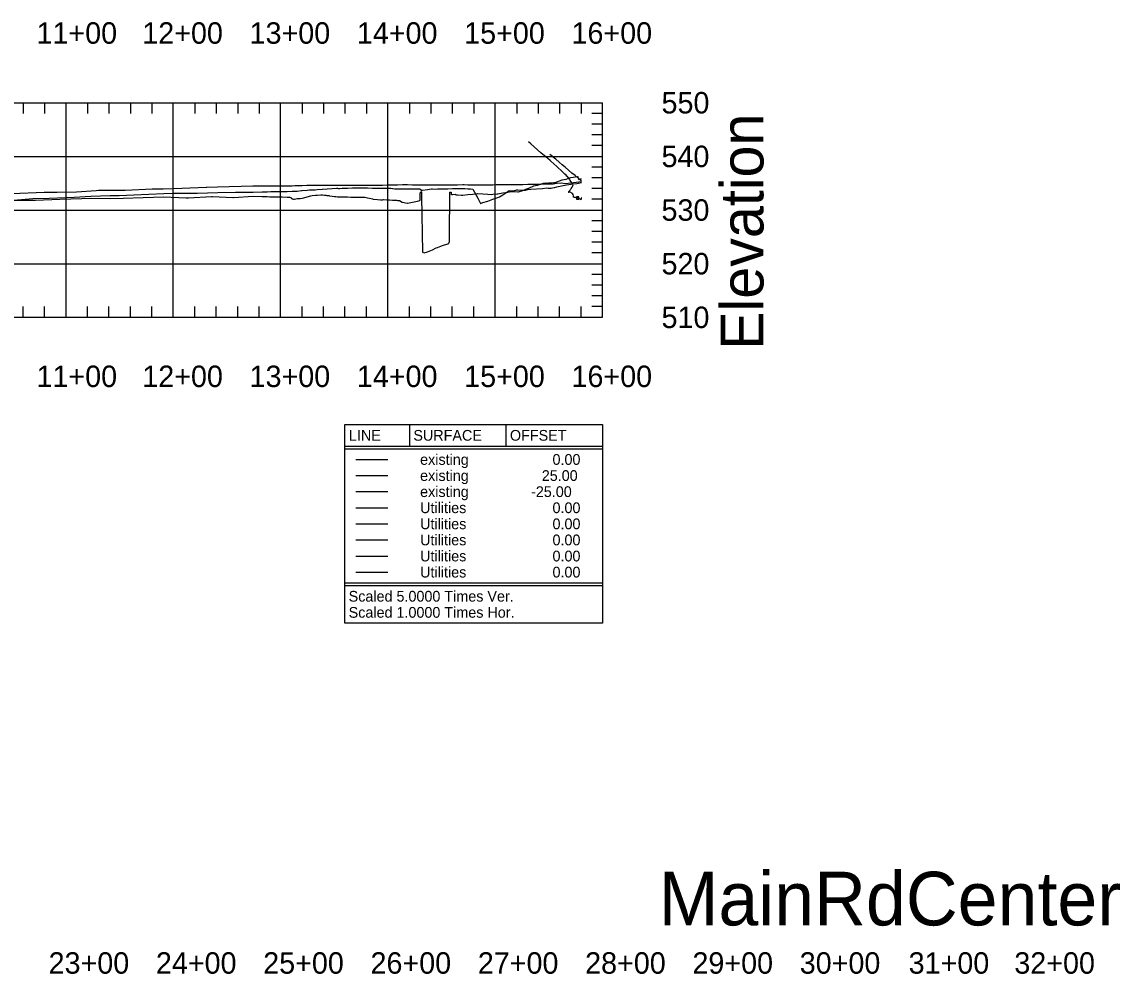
# Model space of a CAD drawing. Extents: x 704797 to 712284, y 374940 to 376945.
# Drawn here: x 709378 to 710402, y 375980 to 376868 of the extents above; entities that cross this region are included whole.
import ezdxf

# ---------------------------------------------------------------- set-up
doc = ezdxf.new("R2010")
doc.units = 0
for name, color, linetype in [('1', 7, 'Continuous'), ('10', 7, 'Continuous'), ('13', 7, 'Continuous'), ('61', 7, 'Continuous'), ('63', 7, 'Continuous'), ('Default_Profile', 7, 'Continuous'), ('Existing', 7, 'Continuous')]:
    doc.layers.add(name, color=color, linetype=linetype)

msp = doc.modelspace()

# ---------------------------------------------------------------- linework, layer by layer
at = {"layer": '10'}
msp.add_lwpolyline([(709899.8, 376703.6), (709899.5, 376703.8), (709899.5, 376702.5), (709899.4, 376701.7), (709897.5, 376703), (709896.9, 376703.5), (709895.6, 376703.6), (709895.5, 376703.6), (709895.3, 376703.6), (709895.1, 376703.6), (709894.8, 376703.7), (709894.2, 376703.9), (709893.3, 376704.1), (709892.5, 376704.3), (709892.5, 376705), (709892.4, 376705.6), (709892.3, 376706.9), (709891.6, 376707.7), (709889.5, 376708.8), (709888.8, 376709), (709888.5, 376709), (709888.3, 376709), (709887.4, 376708.8), (709887.5, 376708.9), (709887.7, 376709.1), (709888.3, 376709.6), (709888.4, 376709.8), (709889, 376710.4), (709889.2, 376710.7), (709889.7, 376711.3), (709889.9, 376711.6), (709890.4, 376712.5), (709891.1, 376713.6), (709891.8, 376715), (709892.3, 376715.8), (709891.9, 376716.4), (709889.3, 376719.7), (709889.2, 376720), (709889, 376720.3), (709888.6, 376721.1), (709886.9, 376723.6), (709886.4, 376724), (709885.6, 376724.7), (709884.5, 376725.7), (709882.2, 376727.8), (709876.9, 376733), (709871.3, 376737.9), (709870.6, 376738.5), (709868.4, 376740.3), (709862.1, 376745.5), (709858.9, 376748.5), (709852.7, 376753.9), (709850.4, 376755.8)], dxfattribs=at)
msp.add_lwpolyline([(709895.3, 376702.5), (709897.3, 376702.5), (709897.3, 376704.5), (709895.3, 376704.5)], close=True, dxfattribs=at)
at = {"layer": '13'}
msp.add_lwpolyline([(709899.8, 376719.3), (709898.6, 376720.4), (709897.2, 376721.6), (709893.9, 376724.4), (709891, 376726.7), (709887.7, 376729.5), (709884.7, 376732.1), (709881.9, 376734.4), (709879, 376736.9), (709875.9, 376739.6), (709873.8, 376741.4), (709872.9, 376742.1), (709870.3, 376744.1)], dxfattribs=at)
at = {"layer": '61'}
for p, q in [((708419.5, 376792.3), (709919.5, 376792.3)), ((709379.5, 376792.3), (709379.5, 376782.3)), ((709399.5, 376792.3), (709399.5, 376782.3)), ((709419.5, 376592.3), (709419.5, 376792.3)), ((709439.5, 376792.3), (709439.5, 376782.3)), ((709459.5, 376792.3), (709459.5, 376782.3)), ((709479.5, 376792.3), (709479.5, 376782.3)), ((709499.5, 376792.3), (709499.5, 376782.3)), ((709519.5, 376592.3), (709519.5, 376792.3)), ((709539.5, 376792.3), (709539.5, 376782.3)), ((709559.5, 376792.3), (709559.5, 376782.3)), ((709579.5, 376792.3), (709579.5, 376782.3)), ((709599.5, 376792.3), (709599.5, 376782.3)), ((709619.5, 376592.3), (709619.5, 376792.3)), ((709639.5, 376792.3), (709639.5, 376782.3)), ((709659.5, 376792.3), (709659.5, 376782.3)), ((709679.5, 376792.3), (709679.5, 376782.3)), ((709699.5, 376792.3), (709699.5, 376782.3)), ((709719.5, 376592.3), (709719.5, 376792.3)), ((709739.5, 376792.3), (709739.5, 376782.3)), ((709759.5, 376792.3), (709759.5, 376782.3)), ((709779.5, 376792.3), (709779.5, 376782.3)), ((709799.5, 376792.3), (709799.5, 376782.3)), ((709819.5, 376592.3), (709819.5, 376792.3)), ((709839.5, 376792.3), (709839.5, 376782.3)), ((709859.5, 376792.3), (709859.5, 376782.3)), ((709879.5, 376792.3), (709879.5, 376782.3)), ((709899.5, 376792.3), (709899.5, 376782.3)), ((709919.5, 376592.3), (709919.5, 376792.3)), ((709919.5, 376782.3), (709909.5, 376782.3)), ((709919.5, 376772.3), (709909.5, 376772.3)), ((709919.5, 376762.3), (709909.5, 376762.3)), ((709919.5, 376752.3), (709909.5, 376752.3)), ((708419.5, 376742.3), (709919.5, 376742.3)), ((709919.5, 376732.3), (709909.5, 376732.3)), ((709919.5, 376722.3), (709909.5, 376722.3)), ((709919.5, 376712.3), (709909.5, 376712.3)), ((709919.5, 376702.3), (709909.5, 376702.3)), ((708419.5, 376692.3), (709919.5, 376692.3)), ((709919.5, 376682.3), (709909.5, 376682.3)), ((709919.5, 376672.3), (709909.5, 376672.3)), ((709919.5, 376662.3), (709909.5, 376662.3)), ((709919.5, 376652.3), (709909.5, 376652.3)), ((708419.5, 376642.3), (709919.5, 376642.3)), ((709919.5, 376632.3), (709909.5, 376632.3)), ((709919.5, 376622.3), (709909.5, 376622.3)), ((709919.5, 376612.3), (709909.5, 376612.3)), ((709379.5, 376592.3), (709379.5, 376602.3)), ((709399.5, 376592.3), (709399.5, 376602.3)), ((709439.5, 376592.3), (709439.5, 376602.3)), ((709459.5, 376592.3), (709459.5, 376602.3)), ((709479.5, 376592.3), (709479.5, 376602.3)), ((709499.5, 376592.3), (709499.5, 376602.3)), ((709539.5, 376592.3), (709539.5, 376602.3)), ((709559.5, 376592.3), (709559.5, 376602.3)), ((709579.5, 376592.3), (709579.5, 376602.3)), ((709599.5, 376592.3), (709599.5, 376602.3)), ((709639.5, 376592.3), (709639.5, 376602.3)), ((709659.5, 376592.3), (709659.5, 376602.3)), ((709679.5, 376592.3), (709679.5, 376602.3)), ((709699.5, 376592.3), (709699.5, 376602.3)), ((709739.5, 376592.3), (709739.5, 376602.3)), ((709759.5, 376592.3), (709759.5, 376602.3)), ((709779.5, 376592.3), (709779.5, 376602.3)), ((709799.5, 376592.3), (709799.5, 376602.3)), ((709839.5, 376592.3), (709839.5, 376602.3)), ((709859.5, 376592.3), (709859.5, 376602.3)), ((709879.5, 376592.3), (709879.5, 376602.3)), ((709899.5, 376592.3), (709899.5, 376602.3)), ((709919.5, 376602.3), (709909.5, 376602.3)), ((708419.5, 376592.3), (709919.5, 376592.3)), ((709739.5, 376492.3), (709739.5, 376472.3)), ((709829.5, 376492.3), (709829.5, 376472.3)), ((709679.5, 376472.3), (709919.5, 376472.3)), ((709679.5, 376469.8), (709919.5, 376469.8)), ((709679.5, 376344.8), (709919.5, 376344.8)), ((709679.5, 376342.3), (709919.5, 376342.3))]:
    msp.add_line(p, q, dxfattribs=at)
msp.add_lwpolyline([(709679.5, 376492.3), (709919.5, 376492.3), (709919.5, 376307.3), (709679.5, 376307.3)], close=True, dxfattribs=at)
at = {"layer": '63'}
for p, q in [((709689.5, 376444.8), (709719.5, 376444.8)), ((709689.5, 376429.8), (709719.5, 376429.8))]:
    msp.add_line(p, q, dxfattribs=at)
for points in [[(709353, 376701.4), (709383.9, 376701.4), (709391, 376701.6), (709413.7, 376702.4), (709434.3, 376702.9), (709443, 376703.3), (709461.3, 376703.1), (709473.1, 376703.3), (709491.5, 376704), (709510.6, 376704.5), (709531.6, 376703.6), (709533, 376703.7), (709533, 376703.7), (709533.1, 376703.7), (709533.1, 376703.7), (709533.2, 376703.7), (709533.2, 376703.7), (709533.6, 376703.7), (709533.8, 376703.6), (709555, 376704.9), (709556, 376705), (709575, 376704), (709575.6, 376704), (709593.8, 376705.3), (709602.3, 376705), (709606.9, 376704.8), (709609.4, 376704.7), (709611.6, 376704.7), (709616.3, 376704.6), (709621, 376704.5), (709625.6, 376704.4), (709628.1, 376704.3), (709629.4, 376703.6), (709629.6, 376703.2), (709630, 376702.9), (709630.3, 376702.8), (709630.6, 376702.7), (709631.4, 376702.5), (709632.4, 376702.5), (709633.6, 376702.6), (709635, 376702.9), (709636.1, 376703.1), (709637.7, 376703), (709639.7, 376703.5), (709641, 376703.8), (709644.3, 376704.7), (709644.3, 376704.7), (709647.8, 376705.5), (709649, 376705.7), (709652.1, 376706.1), (709653.7, 376706.2), (709656.9, 376706.4), (709657.8, 376706.4), (709658.3, 376706.4), (709658.6, 376706.4), (709660.5, 376706.3), (709660.9, 376706.1), (709661.8, 376706), (709662.7, 376705.9), (709663, 376705.9), (709664.4, 376705.7), (709665, 376705.5), (709667.7, 376705.2), (709669.7, 376704.8), (709669.9, 376704.9), (709670.9, 376704.8), (709672.4, 376704.7), (709677, 376704.6), (709677.3, 376704.6), (709681.7, 376704.5), (709685, 376704.4), (709686.4, 376704.4), (709691.1, 376704.4), (709691.9, 376704.3), (709695.7, 376704.3), (709698, 376704.2), (709700.4, 376703.8), (709702.3, 376703.5), (709705.1, 376702.6), (709705.9, 376702.3), (709709.8, 376702), (709712.5, 376701.8), (709714.4, 376701.9), (709715.5, 376702), (709718.5, 376701.8), (709719.1, 376701.7), (709719.8, 376701.7), (709721, 376701.7), (709723.8, 376701.6), (709727.4, 376701.4), (709728.4, 376701.3), (709730.4, 376701.1), (709732.8, 376699.7), (709733.1, 376699.6), (709737.3, 376698.6), (709737.4, 376698.6), (709737.8, 376698.7), (709742.5, 376699.7), (709747.1, 376700.7), (709749.3, 376701.1), (709749.3, 376701.1), (709749.5, 376702.1), (709749.7, 376708.1), (709749.7, 376708.1), (709750.6, 376709.3), (709750.7, 376709.4), (709750.8, 376706.8), (709750.9, 376704.9), (709751.7, 376653.2), (709751.8, 376653.1), (709753.4, 376652.3), (709756.5, 376653.4), (709761, 376655.1), (709761.2, 376655.2), (709764.5, 376657.1), (709765.8, 376657.5), (709770.5, 376659.1), (709775.2, 376660.7), (709776.2, 376661), (709776.7, 376662.3), (709777, 376662.3), (709777, 376667.7), (709777.3, 376708.9), (709777.4, 376708.9), (709777.5, 376708.9), (709778.3, 376709.1), (709778.5, 376707), (709778.6, 376706.5), (709778.7, 376706.7), (709779.8, 376706.9), (709782.1, 376707.2), (709782.8, 376706.5), (709783.7, 376706.6), (709784.5, 376706.6), (709788.2, 376706.2), (709789.2, 376706.3), (709793.9, 376706.8), (709798.5, 376707.2), (709803.1, 376707.6), (709803.2, 376707.6), (709807.9, 376707.4), (709812.6, 376707.1), (709816, 376706.9), (709817.2, 376707), (709821.3, 376707.3), (709821.9, 376707.4), (709826.6, 376708.2), (709831.2, 376709), (709834.6, 376709.5), (709835.9, 376709.5), (709840.6, 376709.4), (709841.3, 376709.4), (709845.3, 376710.6), (709846.7, 376711), (709847.3, 376711.4), (709848.1, 376711.7), (709848.9, 376712), (709849.8, 376712.4), (709849.9, 376712.4), (709850.7, 376712.7), (709851.6, 376713), (709855.5, 376714.8), (709857.1, 376715.2), (709858.9, 376715.6), (709860.8, 376716.1), (709862.6, 376716.6), (709863.9, 376717.1), (709864.6, 376717.2), (709865, 376717.2), (709866.7, 376717.5), (709867.3, 376717.4), (709869.1, 376717.6), (709869.8, 376717.6), (709872.6, 376717.8), (709874.2, 376718), (709875.4, 376718.1), (709882, 376720.3), (709885.7, 376721.2), (709887.2, 376721.6), (709890, 376722.7), (709896.2, 376723.5), (709896.6, 376723.5), (709896.6, 376723.5), (709896.6, 376723.2), (709897, 376720.9), (709899.3, 376721.3), (709899.8, 376721.4)], [(709370.9, 376701.4), (709388.7, 376702.9), (709403.7, 376703.4), (709427, 376704.4), (709442.5, 376705.2), (709460.6, 376705.7), (709469, 376705.9), (709482.8, 376706.4), (709510.7, 376707.7), (709520, 376708.1), (709541.6, 376708.1), (709561, 376708.7), (709577.4, 376708.9), (709593.8, 376709.1), (709602.3, 376709.3), (709606.9, 376709.4), (709610.5, 376709.5), (709611.6, 376709.5), (709614.8, 376709.6), (709616.3, 376709.6), (709621, 376709.6), (709625.6, 376709.6), (709625.7, 376709.6), (709630.3, 376709.8), (709634, 376709.9), (709635, 376710), (709639.1, 376710.4), (709639.7, 376710.5), (709644.3, 376710.9), (709646.5, 376711.1), (709649, 376711.1), (709649.1, 376711.2), (709651.8, 376711.2), (709653.7, 376711.3), (709658.3, 376711.6), (709658.4, 376711.6), (709663, 376712), (709667.7, 376712.3), (709671.6, 376712.6), (709672.4, 376712.6), (709673.6, 376712.5), (709674.8, 376712.5), (709677, 376712.6), (709681.7, 376712.8), (709686.4, 376712.9), (709688.1, 376713), (709691.1, 376713), (709694.5, 376713.1), (709695, 376713.1), (709695.7, 376713.1), (709700.4, 376712.9), (709705.1, 376712.8), (709709.8, 376712.7), (709714.4, 376712.7), (709719.1, 376712.6), (709722.2, 376712.6), (709723.8, 376712.5), (709724, 376712.4), (709725.9, 376712), (709728.4, 376711.9), (709733.1, 376711.9), (709737.8, 376711.9), (709742.5, 376711.9), (709747.1, 376712), (709749.1, 376712), (709751.2, 376710.6), (709751.8, 376710.7), (709756.5, 376711.5), (709760.2, 376712.2), (709761.2, 376712.1), (709764, 376711.7), (709765.8, 376711.9), (709768.5, 376712.1), (709770.5, 376712.1), (709775.2, 376712.2), (709779.8, 376712.3), (709782.4, 376712.4), (709784.5, 376712.3), (709789.2, 376712.3), (709791.3, 376712.3), (709793.9, 376712.1), (709796.4, 376711.9), (709798.5, 376711.8), (709798.7, 376711.7), (709803.2, 376703.4), (709805.8, 376698.5), (709807.9, 376699.2), (709812.6, 376700.7), (709817.2, 376702.3), (709821.9, 376704), (709823.5, 376704.5), (709826.6, 376706.6), (709831.2, 376709.7), (709832.4, 376710.5), (709835.9, 376710.3), (709836.6, 376710.3), (709839.8, 376711.2), (709840.6, 376711.1), (709845.3, 376710.9), (709847.6, 376710.8), (709849.9, 376711.3), (709852.6, 376711.8), (709863.7, 376712.4), (709867.5, 376712.9), (709868.9, 376712.8), (709870.2, 376712.8), (709871.5, 376712.8), (709873, 376712.9), (709874.9, 376713.4), (709876.8, 376713.9), (709882.8, 376715.3), (709885.9, 376715.9), (709892.6, 376716.7), (709895.6, 376717), (709897.2, 376717.3), (709899.8, 376717.9)]]:
    msp.add_lwpolyline(points, dxfattribs=at)
at = {"layer": 'Default_Profile'}
for p, q in [((709689.5, 376414.8), (709719.5, 376414.8)), ((709689.5, 376399.8), (709719.5, 376399.8)), ((709689.5, 376384.8), (709719.5, 376384.8)), ((709689.5, 376369.8), (709719.5, 376369.8)), ((709689.5, 376354.8), (709719.5, 376354.8))]:
    msp.add_line(p, q, dxfattribs=at)
at = {"layer": 'Existing'}
msp.add_line((709689.5, 376459.8), (709719.5, 376459.8), dxfattribs=at)
msp.add_lwpolyline([(709369.1, 376707.8), (709399.2, 376708.9), (709400.6, 376709), (709411.2, 376708.8), (709429.3, 376709.3), (709447.5, 376710.6), (709449.7, 376710.7), (709474.6, 376710.9), (709499.8, 376712.2), (709510, 376712), (709527.4, 376712.8), (709550.1, 376713.6), (709550.6, 376713.6), (709560.8, 376713.9), (709593.6, 376714.7), (709594.8, 376714.8), (709602.3, 376714.8), (709606.9, 376714.8), (709611.6, 376714.8), (709614.5, 376714.8), (709616.3, 376714.8), (709621, 376714.9), (709625.6, 376715), (709630.3, 376715), (709632.9, 376715.1), (709635, 376715.1), (709639.7, 376715.2), (709643.9, 376715.4), (709644.3, 376715.4), (709645.7, 376715.4), (709649, 376715.4), (709653.7, 376715.4), (709658.3, 376715.4), (709663, 376715.4), (709667.7, 376715.4), (709671.7, 376715.4), (709672.4, 376715.4), (709677, 376715.5), (709681.7, 376715.5), (709686.4, 376715.6), (709688.4, 376715.6), (709691.1, 376715.6), (709691.3, 376715.6), (709695.7, 376715.6), (709700.4, 376715.5), (709705.1, 376715.5), (709707.6, 376715.5), (709709.8, 376715.4), (709710.5, 376715.4), (709714.4, 376715.5), (709719.1, 376715.7), (709723.8, 376715.8), (709728.4, 376715.9), (709733.1, 376716), (709733.6, 376716), (709737.1, 376716.1), (709737.8, 376716.1), (709742.5, 376715.9), (709747.1, 376715.8), (709747.9, 376715.8), (709751.8, 376715.8), (709756.5, 376715.8), (709761.2, 376715.8), (709765.8, 376715.8), (709770.5, 376715.8), (709775, 376715.8), (709775.2, 376715.8), (709779.8, 376715.9), (709780.2, 376715.9), (709784.5, 376715.9), (709789.2, 376716), (709790.5, 376716), (709793.9, 376715.9), (709798.5, 376715.9), (709802.6, 376715.9), (709803.2, 376715.9), (709807.9, 376715.9), (709812.6, 376715.9), (709817.2, 376715.9), (709820.4, 376716), (709821.9, 376716), (709822.6, 376716), (709826.6, 376716), (709831.2, 376716.1), (709835.9, 376716.1), (709839, 376716.2), (709840.6, 376716.2), (709845.3, 376716.2), (709849.9, 376716.3), (709862.1, 376716.4), (709873.5, 376716.7), (709876.9, 376717.2), (709881, 376717.5), (709885.1, 376717), (709899.8, 376719)], dxfattribs=at)

# ---------------------------------------------------------------- texts
at = {"layer": '1'}
for s, height, p in [(' LINE ', 10, (709679.5, 376477.3)), (' SURFACE ', 10, (709739.5, 376477.3)), (' OFFSET ', 10, (709829.5, 376477.3)), ('existing', 10, (709749.5, 376454.8)), ('0.00', 10, (709872.9, 376454.8)), ('existing', 10, (709749.5, 376439.8)), ('25.00', 10, (709862.9, 376439.8)), ('existing', 10, (709749.5, 376424.8)), ('-25.00', 10, (709852.9, 376424.8)), ('Utilities', 10, (709749.5, 376409.8)), ('0.00', 10, (709872.9, 376409.8)), ('Utilities', 10, (709749.5, 376394.8)), ('0.00', 10, (709872.9, 376394.8)), ('Utilities', 10, (709749.5, 376379.8)), ('0.00', 10, (709872.9, 376379.8)), ('Utilities', 10, (709749.5, 376364.8)), ('0.00', 10, (709872.9, 376364.8)), ('Utilities', 10, (709749.5, 376349.8)), ('0.00', 10, (709872.9, 376349.8)), ('Scaled 5.0000 Times Ver.', 10, (709682.9, 376327.3)), ('Scaled 1.0000 Times Hor.', 10, (709682.9, 376312.3)), ('MainRdCenter', 50, (709971.8, 376025.5))]:
    msp.add_text(s, height=height, dxfattribs=at).set_placement(p)
at = {"layer": '61'}
for s, p in [('11+00', (709392, 376847.3)), ('12+00', (709490.6, 376847.3)), ('13+00', (709590.6, 376847.3)), ('14+00', (709690.6, 376847.3)), ('15+00', (709790.6, 376847.3)), ('16+00', (709890.6, 376847.3)), ('550', (709974.5, 376782.3)), ('550', (709974.5, 376782.3)), ('540', (709974.5, 376732.3)), ('530', (709974.5, 376682.3)), ('520', (709974.5, 376632.3)), ('510', (709974.5, 376582.3)), ('11+00', (709392, 376527.3)), ('12+00', (709490.6, 376527.3)), ('13+00', (709590.6, 376527.3)), ('14+00', (709690.6, 376527.3)), ('15+00', (709790.6, 376527.3)), ('16+00', (709890.6, 376527.3)), ('23+00', (709403.3, 375980.5)), ('24+00', (709503.3, 375980.5)), ('25+00', (709603.3, 375980.5)), ('26+00', (709703.3, 375980.5)), ('27+00', (709803.3, 375980.5)), ('28+00', (709903.3, 375980.5)), ('29+00', (710003.3, 375980.5)), ('30+00', (710103.3, 375980.5)), ('31+00', (710204.8, 375980.5)), ('32+00', (710303.3, 375980.5))]:
    msp.add_text(s, height=20, dxfattribs=at).set_placement(p)
msp.add_text('Elevation', height=40, rotation=90, dxfattribs=at).set_placement((710069.5, 376562.1))

doc.saveas('drawing.dxf')
